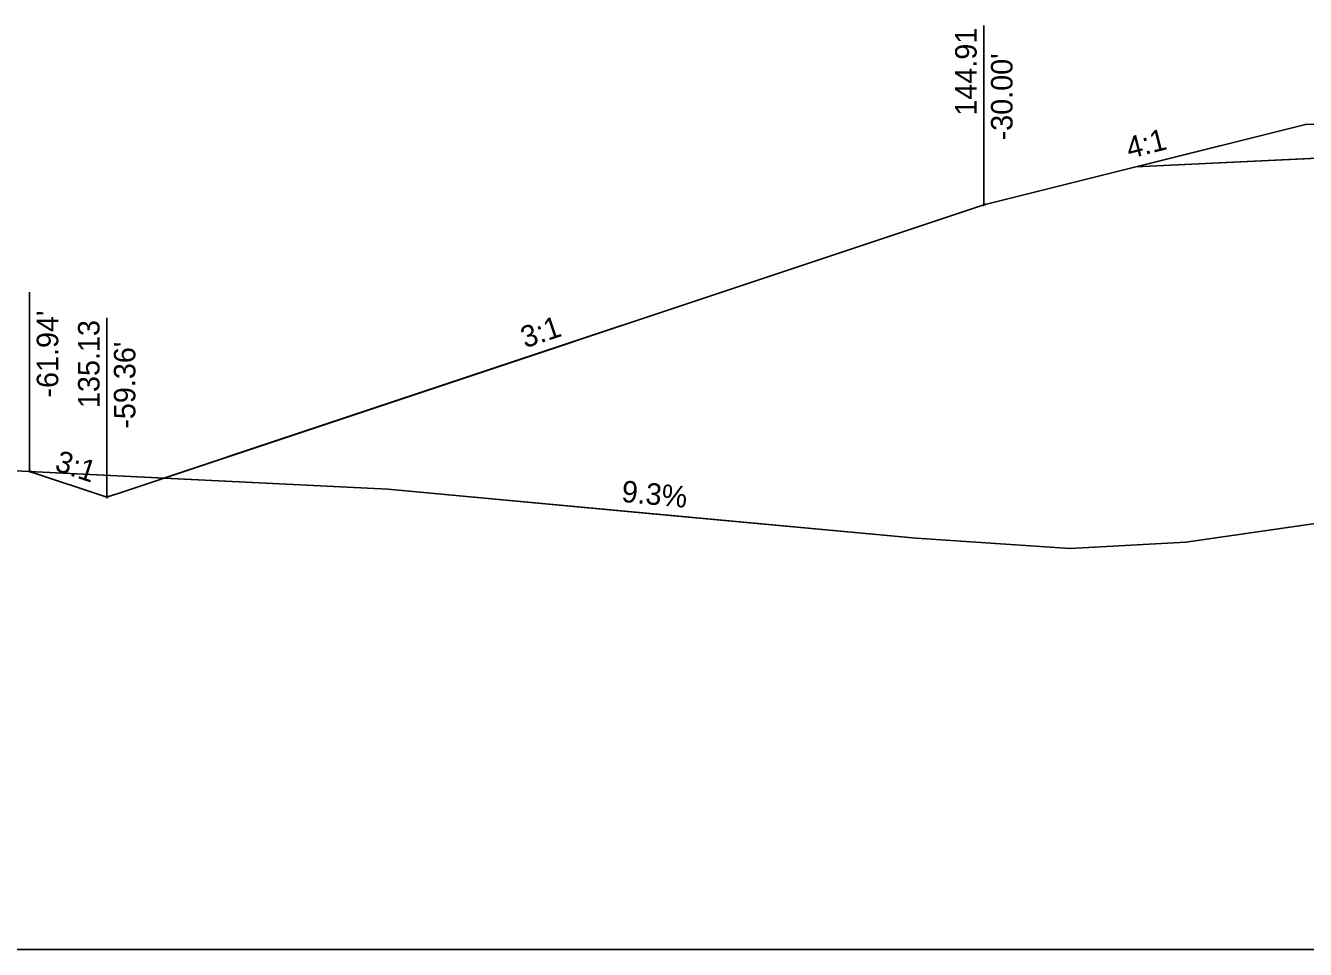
# Model space of a CAD drawing. Extents: x -26 to 4303, y -13 to 10775.
# Drawn here: x 1087.93 to 1130.76, y 4500 to 4530.91 of the extents above; entities that cross this region are included whole.
import ezdxf

# ---------------------------------------------------------------- set-up
doc = ezdxf.new("R2010")
doc.units = 0
for name, color, linetype in [('CONST_DCH', 7, 'Continuous'), ('CONST_LV3', 7, 'Continuous'), ('DTM_CORRIDOR', 7, 'Continuous'), ('DTM_X_GROUND', 7, 'Continuous'), ('SLOPE_STAKES_FILL', 7, 'Continuous'), ('X_ROW', 7, 'Continuous'), ('XS_CELL', 7, 'Continuous'), ('XS_P_GROUND', 7, 'Continuous'), ('XS_P_TX_CLEARZONE', 7, 'Continuous'), ('XS_P_TX_FS_BS', 7, 'Continuous'), ('XS_SHEET_EW_TX_AREA', 7, 'Continuous')]:
    doc.layers.add(name, color=color, linetype=linetype)

msp = doc.modelspace()

# ---------------------------------------------------------------- linework, layer by layer
at = {"layer": 'CONST_LV3'}
msp.add_lwpolyline([(1125.084, 4526.185), (1120, 4524.914)], dxfattribs=at)
at = {"layer": 'DTM_X_GROUND'}
msp.add_lwpolyline([(1000, 4527.047), (1012.653, 4521.36), (1015.589, 4520.9), (1030.406, 4519.586), (1040.857, 4518.334), (1059.518, 4517.394), (1100.052, 4515.401), (1117.74, 4513.76), (1122.892, 4513.417), (1126.763, 4513.627), (1141.699, 4515.779), (1144.696, 4517.139), (1149.906, 4516.828), (1149.956, 4516.833), (1176.709, 4519.611), (1183.124, 4519.79), (1194.202, 4520.766), (1195.632, 4520.835), (1210.279, 4520.767), (1231.863, 4520.749), (1269.14, 4520.527), (1289.173, 4520.495), (1300, 4520.407)], dxfattribs=at)
at = {"layer": 'X_ROW'}
msp.add_line((1136, 4527.814), (1130.762, 4527.605), dxfattribs=at)
at = {"layer": 'XS_CELL'}
msp.add_line((1000, 4500), (1150, 4500), dxfattribs=at)
at = {"layer": 'XS_P_GROUND'}
for points in [[(1130.762, 4527.605), (1120, 4524.914), (1095.829, 4516.858), (1091.263, 4515.336), (1090.644, 4515.13)], [(1090.644, 4515.13), (1088.062, 4515.991), (1088.062, 4515.991), (1088.062, 4515.991)]]:
    msp.add_lwpolyline(points, dxfattribs=at)
at = {"layer": 'XS_P_TX_CLEARZONE'}
for p, q in [((1120, 4524.914), (1120, 4530.914)), ((1120, 4524.914), (1120, 4530.914)), ((1088.062, 4515.991), (1088.062, 4521.991)), ((1088.062, 4515.991), (1088.062, 4521.991)), ((1088.062, 4515.991), (1088.062, 4521.991)), ((1090.644, 4515.13), (1090.644, 4521.13)), ((1090.644, 4515.13), (1090.644, 4521.13))]:
    msp.add_line(p, q, dxfattribs=at)
at = {"layer": 'XS_SHEET_EW_TX_AREA'}
for points in [[(1092.563, 4515.77), (1100.052, 4515.401), (1108.896, 4514.581), (1117.74, 4513.76), (1122.892, 4513.417), (1126.763, 4513.627), (1141.699, 4515.779), (1144.696, 4517.139), (1149.956, 4516.833), (1176.709, 4519.611), (1183.124, 4519.79), (1188.663, 4520.278), (1194.202, 4520.766), (1195.632, 4520.835), (1199.895, 4520.821), (1180, 4527.447), (1178.272, 4527.879), (1166, 4528.149), (1150, 4527.383), (1125.084, 4526.185), (1120, 4524.914)], [(1125.084, 4526.185), (1134, 4526.613), (1134.005, 4527.334), (1136, 4527.377), (1136, 4527.814), (1130.762, 4527.605)], [(1088.062, 4515.991), (1092.563, 4515.77), (1091.263, 4515.336), (1090.644, 4515.13)]]:
    msp.add_lwpolyline(points, close=True, dxfattribs=at)

# ---------------------------------------------------------------- texts
at = {"layer": 'CONST_DCH'}
msp.add_text('X', height=0.12, dxfattribs=at).set_placement((1090.605, 4515.07))
at = {"layer": 'DTM_CORRIDOR'}
msp.add_text('X', height=0.12, dxfattribs=at).set_placement((1088.023, 4515.931))
at = {"layer": 'SLOPE_STAKES_FILL'}
msp.add_text('X', height=0.12, dxfattribs=at).set_placement((1119.961, 4524.854))
at = {"layer": 'XS_P_TX_CLEARZONE'}
for s, p in [('144.91', (1119.76, 4527.9)), ('144.91', (1119.76, 4527.9)), ("-30.00'", (1120.96, 4527.072)), ("-30.00'", (1120.96, 4527.072)), ("-61.94'", (1089.022, 4518.466)), ("-61.94'", (1089.022, 4518.466)), ("-61.94'", (1089.022, 4518.466)), ('135.13', (1090.404, 4518.116)), ('135.13', (1090.404, 4518.116)), ("-59.36'", (1091.604, 4517.424)), ("-59.36'", (1091.604, 4517.424))]:
    msp.add_text(s, height=0.72, rotation=90, dxfattribs=at).set_placement(p)
at = {"layer": 'XS_P_TX_FS_BS'}
for s, rotation, p in [('4:1', 14.1906, (1124.872, 4526.456)), ('3:1', 18.4332, (1104.646, 4520.113)), ('3:1', 341.5651, (1088.867, 4516.039)), ('9.3%', 354.697, (1107.855, 4514.978))]:
    msp.add_text(s, height=0.72, rotation=rotation, dxfattribs=at).set_placement(p)

doc.saveas('drawing.dxf')
